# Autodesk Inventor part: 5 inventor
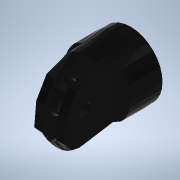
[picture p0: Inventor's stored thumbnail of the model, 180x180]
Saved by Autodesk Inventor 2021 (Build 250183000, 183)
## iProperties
Created: 2022-10
Part Number: 5 inventor
Material: Genérico
Document SubType Name: Modeling
Designer: Yair Obed
Density: 1 g/cm^3
Appearance: Valor por defecto
Author: Yair Obed
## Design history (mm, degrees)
node "5"
  node "MeshFeature1"
